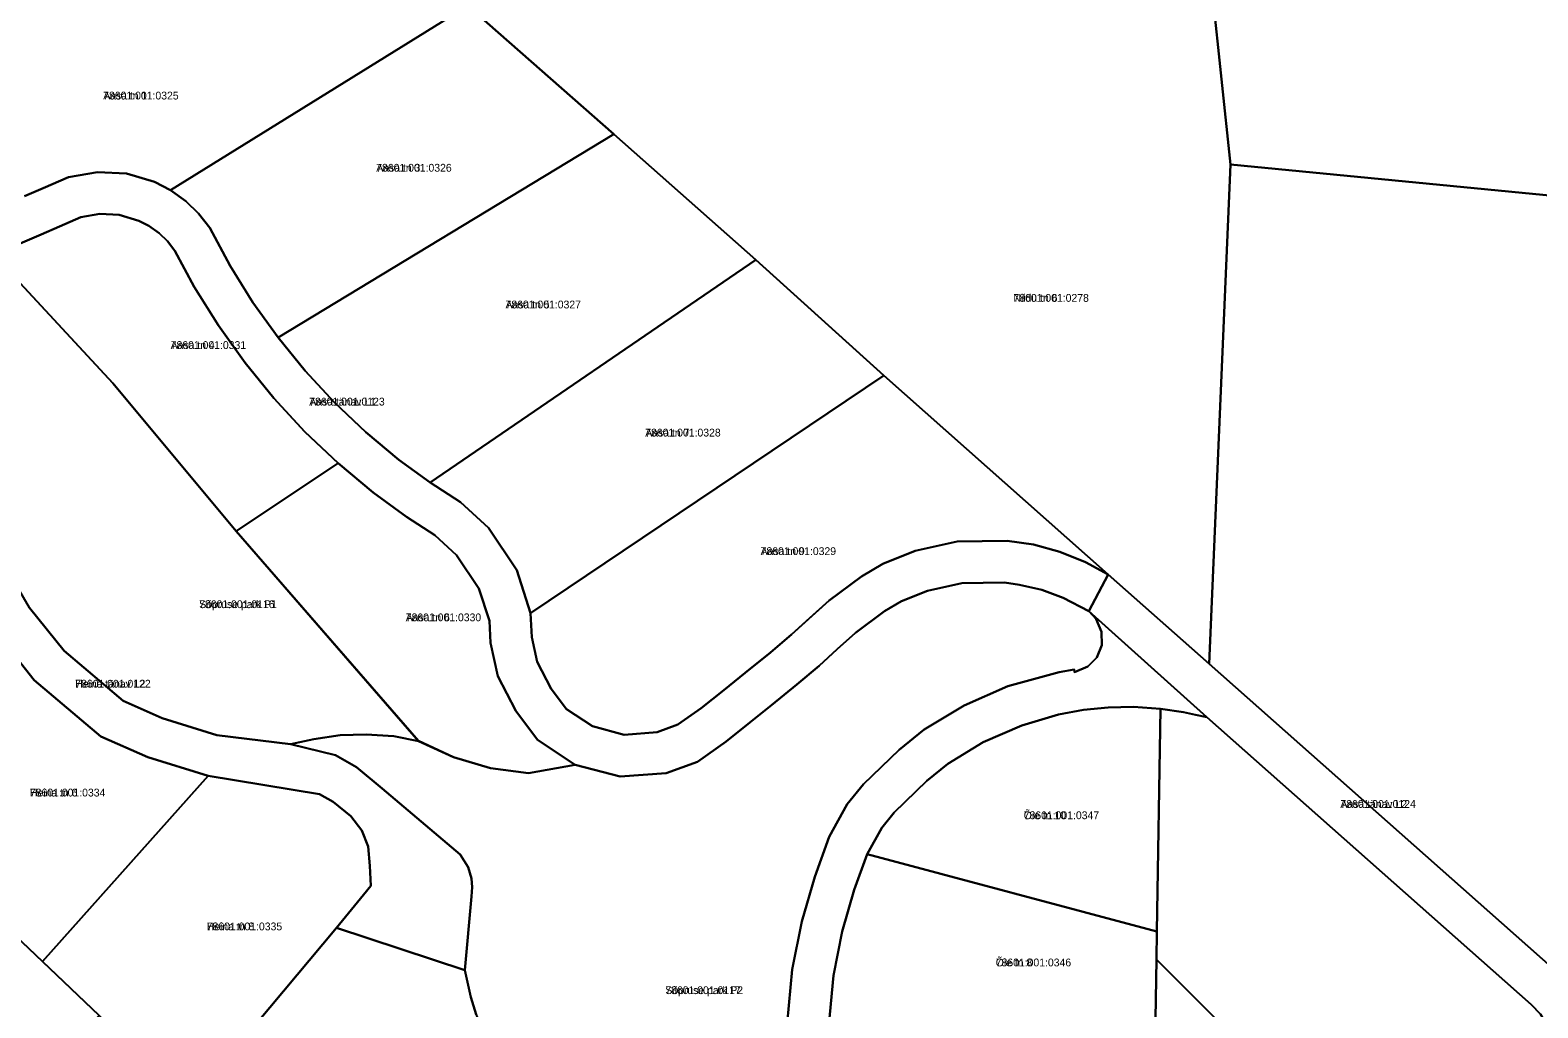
# Model space of a CAD drawing. Extents: x 587616 to 632239, y 6547421 to 6574977.
# Drawn here: x 621332.9 to 621622.8, y 6560022.9 to 6560210.9 of the extents above; entities that cross this region are included whole.
import ezdxf

# ---------------------------------------------------------------- set-up
doc = ezdxf.new("R2010")
doc.units = 0
for name, color, linetype in [('L_AADRESS', 7, 'Continuous'), ('PIIR', 7, 'Continuous'), ('TUNNUS', 7, 'Continuous')]:
    doc.layers.add(name, color=color, linetype=linetype)

msp = doc.modelspace()

# ---------------------------------------------------------------- linework, layer by layer
at = {"layer": 'PIIR'}
for points in [[(621658.9, 6560268.05), (621655.81, 6560188.24), (621655.4, 6560176.16), (621563.71, 6560185.07), (621560.25, 6560217.93), (621560.52, 6560228.25), (621560.9, 6560242.33), (621561.7, 6560272.57)], [(621560.52, 6560228.25), (621560.25, 6560217.93), (621563.71, 6560185.07), (621559.61, 6560089.04), (621540.2, 6560106.23), (621497.03, 6560144.49), (621472.42, 6560166.7), (621445.12, 6560190.86), (621417.05, 6560215.56), (621414.17, 6560218.09), (621459.98, 6560221.82)], [(621380.6, 6560151.78), (621375.77, 6560158.53), (621371.39, 6560165.56), (621367.47, 6560172.86), (621365.32, 6560175.63), (621362.86, 6560178.02), (621359.94, 6560180.1), (621417.05, 6560215.56), (621445.12, 6560190.86)], [(621445.12, 6560190.86), (621472.42, 6560166.7), (621409.83, 6560123.9), (621403.83, 6560128.29), (621397.47, 6560133.6), (621391.46, 6560139.3), (621385.83, 6560145.37), (621380.6, 6560151.78)], [(621563.71, 6560185.07), (621655.4, 6560176.16), (621655.81, 6560188.24), (621755.65, 6560176.82), (621772.73, 6560169.1), (621987.09, 6560144.91), (621990.36, 6560081.41), (621977, 6560081.92), (621975.93, 6560047.12), (621968.66, 6560036.49), (621942.28, 6560039.14), (621707.79, 6560064.01), (621639.56, 6560071.24), (621633.19, 6560023.8), (621559.61, 6560089.04)], [(621392.15, 6560127.62), (621372.57, 6560114.56), (621348.82, 6560142.99), (621327.75, 6560165.78), (621328.34, 6560167.26), (621329.32, 6560168.57), (621331.01, 6560169.83), (621335.07, 6560171.6), (621338.6, 6560173.14), (621342.67, 6560174.9), (621346.35, 6560175.56), (621350.08, 6560175.35), (621353.83, 6560174.25), (621355.77, 6560173.25), (621357.72, 6560171.86), (621359.34, 6560170.28), (621360.74, 6560168.48), (621364.47, 6560161.55), (621369.12, 6560154.09), (621374.24, 6560146.92), (621379.79, 6560140.12), (621385.77, 6560133.67)], [(621472.42, 6560166.7), (621497.03, 6560144.49), (621429.14, 6560098.8), (621426.47, 6560107.03), (621421.05, 6560115.18), (621415.65, 6560120.14), (621409.83, 6560123.9)], [(621407.59, 6560074.19), (621402.84, 6560075.14), (621397.51, 6560075.47), (621392.51, 6560075.33), (621387.5, 6560074.59), (621382.98, 6560073.57), (621368.85, 6560075.36), (621358.34, 6560078.58), (621350.81, 6560081.92), (621339.47, 6560091.52), (621332.84, 6560099.8), (621329.33, 6560105.78), (621327.01, 6560111.06), (621325.22, 6560116.58), (621324.06, 6560122.08), (621323.25, 6560141.64), (621323.6, 6560144.93), (621325, 6560151.13), (621327.11, 6560158.61), (621327.51, 6560164.24), (621327.75, 6560165.78), (621348.82, 6560142.99), (621372.57, 6560114.56)], [(621540.2, 6560106.23), (621535.8, 6560108.59), (621530.85, 6560110.58), (621525.81, 6560111.99), (621520.76, 6560112.69), (621511.12, 6560112.54), (621503.05, 6560110.78), (621496.88, 6560108.28), (621492.73, 6560105.83), (621486.56, 6560101.24), (621482.78, 6560097.81), (621479.31, 6560094.67), (621475.23, 6560091.24), (621470.39, 6560087.31), (621466.27, 6560083.97), (621461.96, 6560080.55), (621457.47, 6560077.37), (621453.49, 6560075.9), (621447.12, 6560075.42), (621441.02, 6560077.04), (621436.05, 6560080.32), (621433.09, 6560084.26), (621430.43, 6560089.44), (621429.39, 6560094.16), (621429.14, 6560098.8), (621497.03, 6560144.49)], [(621372.57, 6560114.56), (621392.15, 6560127.62), (621398.9, 6560121.98), (621405.3, 6560117.31), (621410.74, 6560113.79), (621414.92, 6560109.94), (621419.2, 6560103.52), (621421.21, 6560097.33), (621421.44, 6560093.08), (621422.84, 6560086.7), (621426.29, 6560079.99), (621430.49, 6560074.41), (621437.7, 6560069.65), (621428.75, 6560068.05), (621421.41, 6560069.01), (621414.3, 6560071.08), (621407.59, 6560074.21)], [(621536.44, 6560099.15), (621540.2, 6560106.23), (621559.61, 6560089.04), (621633.19, 6560023.8), (621630.45, 6559908.6), (621626.31, 6559895.58), (621623.07, 6559813.27), (621623.06, 6559791.54), (621613.88, 6559788.46), (621614.76, 6559790.78), (621615.13, 6559793.22), (621615.42, 6559813.44), (621619.1, 6559887.24), (621622.52, 6559911.82), (621622.89, 6559927.25), (621625.01, 6560016.97), (621624.82, 6560018.4), (621624.34, 6560019.9), (621623.31, 6560021.7), (621621.48, 6560023.54), (621559.14, 6560078.76)], [(621328.79, 6560038.03), (621309.89, 6560056.15), (621297.68, 6560067.81), (621326.25, 6560095.25), (621333.7, 6560085.93), (621346.52, 6560075.06), (621355.54, 6560071.07), (621367.17, 6560067.51), (621335.3, 6560031.84)], [(621493.83, 6560052.43), (621496.64, 6560057.54), (621499.04, 6560060.44), (621505.32, 6560066.56), (621509.37, 6560069.83), (621516.16, 6560073.97), (621523.56, 6560077.19), (621530.65, 6560079.3), (621535.4, 6560080.17), (621540.2, 6560080.66), (621545.03, 6560080.75), (621550.22, 6560080.41), (621549.52, 6560037.6)], [(621550.22, 6560080.41), (621554.62, 6560079.78), (621556.99, 6560079.25), (621559.14, 6560078.76), (621621.48, 6560023.54), (621623.31, 6560021.7), (621624.34, 6560019.9), (621624.82, 6560018.4), (621625.01, 6560016.97), (621622.89, 6559927.25), (621622.52, 6559911.82), (621620.61, 6559909.96), (621617.69, 6559907.06), (621605.37, 6559902.99), (621608.41, 6559927.16), (621604.55, 6559947.22), (621590.3, 6559982.41), (621572.92, 6560008.78), (621549.43, 6560032.17), (621549.52, 6560037.6)], [(621363.58, 6560004.5), (621346.22, 6560021.46), (621335.3, 6560031.84), (621367.17, 6560067.51), (621388.54, 6560064.01), (621391.19, 6560062.51), (621394.58, 6560059.76), (621396.67, 6560057.03), (621397.89, 6560053.95), (621398.24, 6560050.2), (621398.45, 6560046.35), (621397.05, 6560044.66), (621391.8, 6560038.3)], [(621486.6, 6560009.93), (621486.49, 6560019.59), (621487.35, 6560029.14), (621489.03, 6560037.61), (621491.36, 6560045.61), (621493.83, 6560052.43), (621549.52, 6560037.6), (621549.43, 6560032.17), (621549.06, 6560009.34)], [(621295.15, 6560004.21), (621328.79, 6560038.03), (621335.3, 6560031.84), (621346.22, 6560021.46), (621312.68, 6559987.24)], [(621391.8, 6560038.3), (621416.5, 6560030.15), (621417.65, 6560024.98), (621418.65, 6560021.64), (621420.16, 6560017.54), (621422.98, 6560011.59), (621424.85, 6560008.43), (621416.95, 6559999.58), (621397.47, 6559972.15), (621382, 6559986.81), (621363.58, 6560004.5)], [(621548.5, 6559975.1), (621549.06, 6560009.34), (621549.43, 6560032.17), (621572.92, 6560008.78), (621590.3, 6559982.41), (621604.55, 6559947.22), (621608.41, 6559927.16), (621605.37, 6559902.99), (621573.48, 6559892.9), (621551.32, 6559885.6), (621549.78, 6559885.98), (621548.69, 6559887.36), (621548.02, 6559891.83), (621545.71, 6559902.38), (621541.97, 6559912.96), (621540.87, 6559929.64), (621547.76, 6559929.77)]]:
    msp.add_lwpolyline(points, close=True, dxfattribs=at)
for points in [[(621417.05, 6560215.56), (621359.94, 6560180.1), (621356.82, 6560181.71), (621351.45, 6560183.29), (621345.86, 6560183.6), (621340.34, 6560182.61), (621335.41, 6560180.48), (621331.87, 6560178.93)], [(621331.87, 6560178.93), (621335.41, 6560180.48), (621340.34, 6560182.61), (621345.86, 6560183.6), (621351.45, 6560183.29), (621356.82, 6560181.71), (621359.94, 6560180.1), (621362.86, 6560178.02), (621365.32, 6560175.63), (621367.47, 6560172.86), (621371.39, 6560165.56), (621375.77, 6560158.53), (621380.6, 6560151.78), (621385.83, 6560145.37), (621391.46, 6560139.3), (621397.47, 6560133.6), (621403.83, 6560128.29), (621409.83, 6560123.9), (621415.65, 6560120.14), (621421.05, 6560115.18), (621426.47, 6560107.03), (621429.14, 6560098.8), (621429.39, 6560094.16), (621430.43, 6560089.44), (621433.09, 6560084.26), (621436.05, 6560080.32), (621441.02, 6560077.04), (621447.12, 6560075.42), (621453.49, 6560075.9), (621457.47, 6560077.37), (621461.96, 6560080.55), (621466.27, 6560083.97), (621470.39, 6560087.31), (621475.23, 6560091.24), (621479.31, 6560094.67), (621486.56, 6560101.24), (621492.73, 6560105.83), (621496.88, 6560108.28), (621503.05, 6560110.78), (621511.12, 6560112.54), (621520.76, 6560112.69), (621525.81, 6560111.99), (621530.85, 6560110.58), (621535.8, 6560108.59), (621540.2, 6560106.23), (621536.44, 6560099.15), (621531.55, 6560101.75), (621527.39, 6560103.25), (621523.15, 6560104.25), (621520.26, 6560104.67), (621512.04, 6560104.54), (621505.42, 6560103.1), (621500.44, 6560101.09), (621497.16, 6560099.16), (621491.62, 6560095.02), (621488.08, 6560091.89), (621484.62, 6560088.67), (621480.32, 6560085.05), (621475.43, 6560081.12), (621471.27, 6560077.74), (621466.76, 6560074.14), (621461.24, 6560070.23), (621455.21, 6560068), (621446.36, 6560067.36), (621437.7, 6560069.65), (621430.49, 6560074.41), (621426.29, 6560079.99), (621422.84, 6560086.7), (621421.44, 6560093.08), (621421.21, 6560097.33), (621419.2, 6560103.52), (621414.92, 6560109.94), (621410.74, 6560113.79), (621405.3, 6560117.31), (621398.9, 6560121.98), (621392.15, 6560127.62), (621385.77, 6560133.67), (621379.79, 6560140.12), (621374.24, 6560146.92), (621369.12, 6560154.09), (621364.47, 6560161.55), (621360.74, 6560168.48), (621359.34, 6560170.28), (621357.72, 6560171.86), (621355.77, 6560173.25), (621353.83, 6560174.25), (621350.08, 6560175.35), (621346.35, 6560175.56), (621342.67, 6560174.9), (621338.6, 6560173.14), (621335.07, 6560171.6), (621331.01, 6560169.83)], [(621418.65, 6560021.64), (621417.65, 6560024.98), (621416.5, 6560030.15), (621417.81, 6560044.29), (621417.91, 6560046.11), (621417.78, 6560047.79), (621417.15, 6560049.95), (621415.61, 6560052.4), (621400.6, 6560065.06), (621395.7, 6560069.15), (621391.66, 6560071.51), (621382.98, 6560073.57), (621387.5, 6560074.59), (621392.51, 6560075.33), (621397.51, 6560075.47), (621402.84, 6560075.14), (621407.59, 6560074.19), (621414.3, 6560071.08), (621421.41, 6560069.01), (621428.75, 6560068.05), (621437.7, 6560069.65), (621446.36, 6560067.36), (621455.21, 6560068), (621461.24, 6560070.23), (621466.76, 6560074.14), (621471.27, 6560077.74), (621475.43, 6560081.12), (621480.32, 6560085.05), (621484.62, 6560088.67), (621488.08, 6560091.89), (621491.62, 6560095.02), (621497.16, 6560099.16), (621500.44, 6560101.09), (621505.42, 6560103.1), (621512.04, 6560104.54), (621520.26, 6560104.67), (621523.15, 6560104.25), (621527.39, 6560103.25), (621531.55, 6560101.75), (621536.44, 6560099.19), (621537.86, 6560097.66), (621538.89, 6560095.23), (621538.93, 6560092.66), (621537.96, 6560090.28), (621536.23, 6560088.55), (621533.73, 6560087.44), (621533.61, 6560087.98), (621530.77, 6560087.46), (621520.9, 6560084.75), (621512.5, 6560081.06), (621504.78, 6560076.39), (621500, 6560072.54), (621493.13, 6560065.88), (621490, 6560062.06), (621486.53, 6560055.77), (621483.75, 6560048.1), (621481.26, 6560039.5), (621479.42, 6560030.27), (621478.49, 6560019.91)], [(621332.84, 6560099.8), (621339.47, 6560091.52), (621350.81, 6560081.92), (621358.34, 6560078.58), (621368.85, 6560075.36), (621382.98, 6560073.57), (621391.66, 6560071.51), (621395.7, 6560069.15), (621400.6, 6560065.06), (621415.61, 6560052.4), (621417.15, 6560049.95), (621417.78, 6560047.79), (621417.91, 6560046.11), (621417.81, 6560044.29), (621416.5, 6560030.15), (621391.8, 6560038.3), (621397.05, 6560044.66), (621398.45, 6560046.35), (621398.24, 6560050.2), (621397.89, 6560053.95), (621396.67, 6560057.03), (621394.58, 6560059.76), (621391.19, 6560062.51), (621388.54, 6560064.01), (621367.17, 6560067.51), (621355.54, 6560071.07), (621346.52, 6560075.06), (621333.7, 6560085.93), (621326.25, 6560095.25)], [(621478.49, 6560019.91), (621479.42, 6560030.27), (621481.26, 6560039.5), (621483.75, 6560048.1), (621486.53, 6560055.77), (621490, 6560062.06), (621493.13, 6560065.88), (621500, 6560072.54), (621504.78, 6560076.39), (621512.5, 6560081.06), (621520.9, 6560084.75), (621530.77, 6560087.46), (621533.61, 6560087.98), (621533.73, 6560087.44), (621536.23, 6560088.55), (621537.96, 6560090.28), (621538.93, 6560092.66), (621538.89, 6560095.23), (621537.86, 6560097.66), (621536.44, 6560099.19), (621559.14, 6560078.76), (621556.99, 6560079.25), (621554.62, 6560079.78), (621550.22, 6560080.41), (621545.03, 6560080.75), (621540.2, 6560080.66), (621535.4, 6560080.17), (621530.65, 6560079.3), (621523.56, 6560077.19), (621516.16, 6560073.97), (621509.37, 6560069.83), (621505.32, 6560066.56), (621499.04, 6560060.44), (621496.64, 6560057.54), (621493.83, 6560052.43), (621491.36, 6560045.61), (621489.03, 6560037.61), (621487.35, 6560029.14), (621486.49, 6560019.59)]]:
    msp.add_lwpolyline(points, dxfattribs=at)

# ---------------------------------------------------------------- texts
at = {"layer": 'L_AADRESS'}
for s, p in [('Aasa tn 1', (621346.98, 6560197.55)), ('Aasa tn 3', (621399.47, 6560183.67)), ('Aasa tn 5', (621424.32, 6560157.38)), ('Niidu tn 6', (621521.96, 6560158.65)), ('Aasa tn 4', (621359.95, 6560149.58)), ('Aasa tänav L1', (621386.59, 6560138.71)), ('Aasa tn 7', (621451.18, 6560132.75)), ('Aasa tn 9', (621473.36, 6560109.96)), ('Sõpruse park P1', (621365.42, 6560099.76)), ('Aasa tn 6', (621405.14, 6560097.23)), ('Heina tänav L2', (621341.61, 6560084.47)), ('Heina tn 6', (621332.89, 6560063.54)), ('Aasa tänav L2', (621584.81, 6560061.35)), ('Õie tn 10', (621523.93, 6560059.18)), ('Heina tn 8', (621366.88, 6560037.81)), ('Õie tn 8', (621518.55, 6560030.88)), ('Sõpruse park P2', (621455.04, 6560025.55))]:
    msp.add_text(s, height=1.5, dxfattribs=at).set_placement(p)
at = {"layer": 'TUNNUS'}
for s, p in [('78601:001:0325', (621346.98, 6560197.55)), ('78601:001:0326', (621399.47, 6560183.67)), ('78601:001:0327', (621424.32, 6560157.38)), ('78601:001:0278', (621521.96, 6560158.65)), ('78601:001:0331', (621359.95, 6560149.58)), ('78601:001:0123', (621386.59, 6560138.71)), ('78601:001:0328', (621451.18, 6560132.75)), ('78601:001:0329', (621473.36, 6560109.96)), ('78601:001:0116', (621365.42, 6560099.76)), ('78601:001:0330', (621405.14, 6560097.23)), ('78601:001:0122', (621341.61, 6560084.47)), ('78601:001:0334', (621332.89, 6560063.54)), ('78601:001:0124', (621584.81, 6560061.35)), ('78601:001:0347', (621523.93, 6560059.18)), ('78601:001:0335', (621366.88, 6560037.81)), ('78601:001:0346', (621518.55, 6560030.88)), ('78601:001:0117', (621455.04, 6560025.55))]:
    msp.add_text(s, height=1.5, dxfattribs=at).set_placement(p)

doc.saveas('drawing.dxf')
